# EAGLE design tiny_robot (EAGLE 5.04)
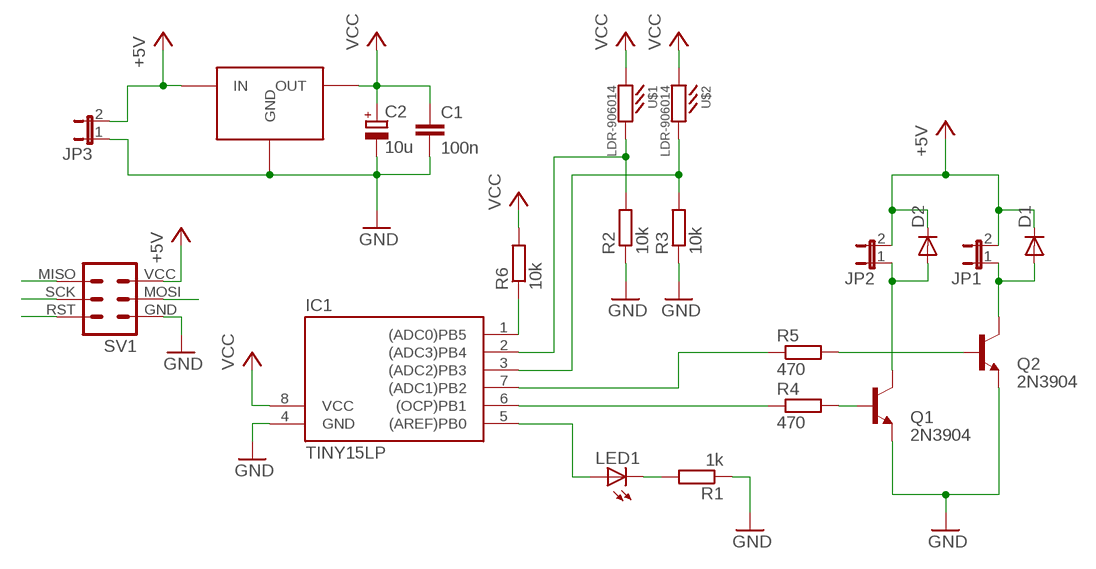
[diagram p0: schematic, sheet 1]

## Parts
C1  100n  C-EU025-025X050  [C025-025X050]
C2  10u  CPOL-EUE2,5-6E  [E2,5-6E]
D1  1N4148DO35-7  [DO35-7]
D2  1N4148DO35-7  [DO35-7]
IC1  TINY15LP  [DIL08]
JP1  JP1E  [JP1]
JP2  JP1E  [JP1]
JP3  JP1E  [JP1]
LED1  LED3MM  [LED3MM]
Q1  2N3904  [TO92]
Q2  2N3904  [TO92]
R1  1k  R-EU_0207/2V  [0207/2V]
R2  10k  R-EU_0207/2V  [0207/2V]
R3  10k  R-EU_0207/2V  [0207/2V]
R4  470  R-EU_0207/2V  [0207/2V]
R5  470  R-EU_0207/2V  [0207/2V]
R6  10k  R-EU_0207/2V  [0207/2V]
SV1  MA03-2  [MA03-2]
U$1  LDR-906014  [LDR-906014]
U$2  LDR-906014  [LDR-906014]
U$3  MCP1700  [TO92]

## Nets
+5V: D1.C D2.C JP1.2 JP2.2 JP3.2 SV1.VCC U$3.2(IN)
GND: C1.2 C2.- IC1.4(GND) JP3.1 Q1.3(E) Q2.3(E) R1.1 R2.1 R3.1 SV1.GND U$3.3(GND)
MISO: IC1.6((OCP)PB1) R4.1 SV1.MISO
MOSI: IC1.5((AREF)PB0) LED1.A SV1.MOSI
N$2: LED1.K(C) R1.2
N$3: Q1.2(B) R4.2
N$4: Q2.2(B) R5.2
N$11: D2.A JP2.1 Q1.1(C)
N$12: D1.A JP1.1 Q2.1(C)
N$13: IC1.3((ADC2)PB3) R3.2 U$2.P$2
N$15: IC1.2((ADC3)PB4) R2.2 U$1.P$2
RST: IC1.1((ADC0)PB5) R6.1 SV1.RST
SCK: IC1.7((ADC1)PB2) R5.1 SV1.SCK
VCC: C1.1 C2.+ IC1.8(VCC) R6.2 U$1.P$1 U$2.P$1 U$3.1(OUT)

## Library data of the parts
C1 = rcl:C-EU: CAPACITOR, European symbol
C2 = rcl:CPOL-EU: POLARIZED CAPACITOR, European symbol
D1 D2 = diode:1N4148: DIODE
IC1 = atmel:TINY15L: MICROCONTROLLER 2.7 V 1 Kbytes FLASH 64 bytes EEPROM 4-channel 10 bit ADC
JP1-JP3 = jumper:JP1E: JUMPER
LED1 = led:LED: LED
Q1 Q2 = transistor-npn:2N3904: NPN Transistor
R1-R6 = rcl:R-EU_: RESISTOR, European symbol
SV1 = alex:MA03-2: PIN HEADER
U$1 U$2 = alex:LDR-906014
U$3 = alex:MCP1700

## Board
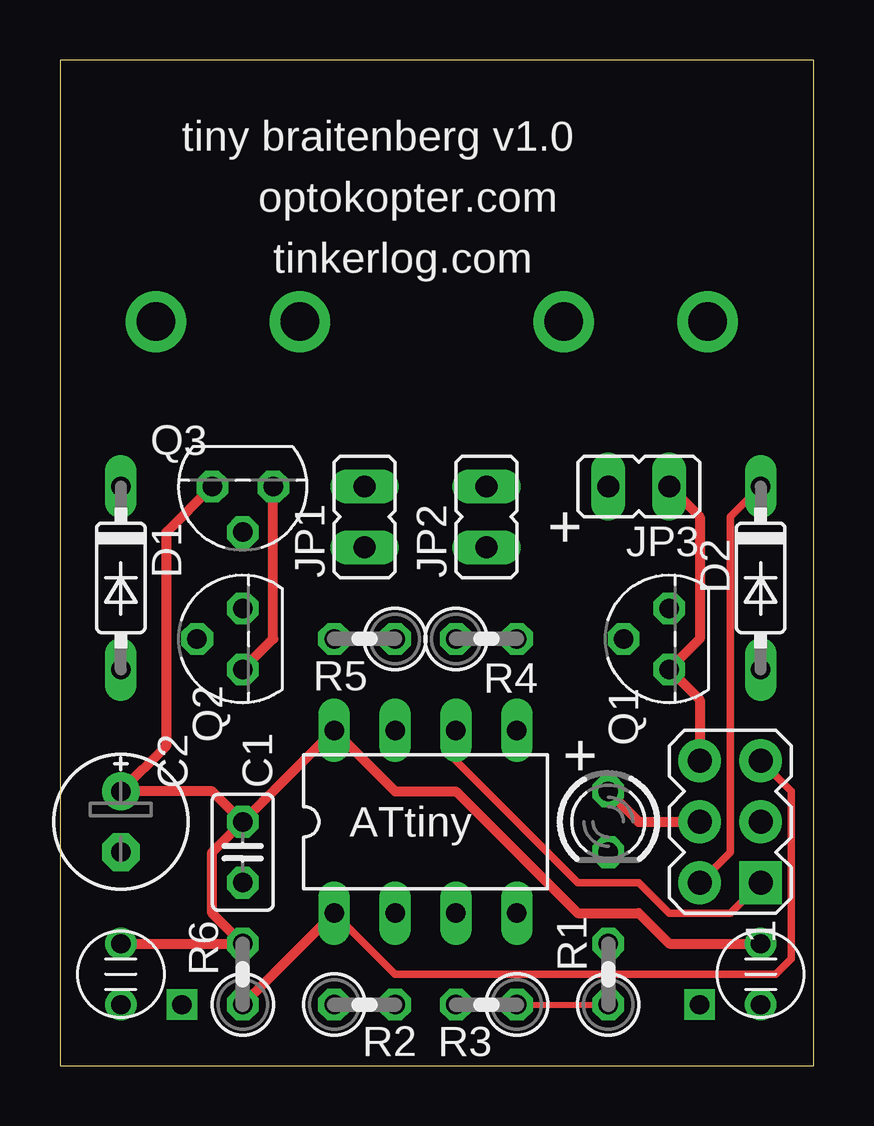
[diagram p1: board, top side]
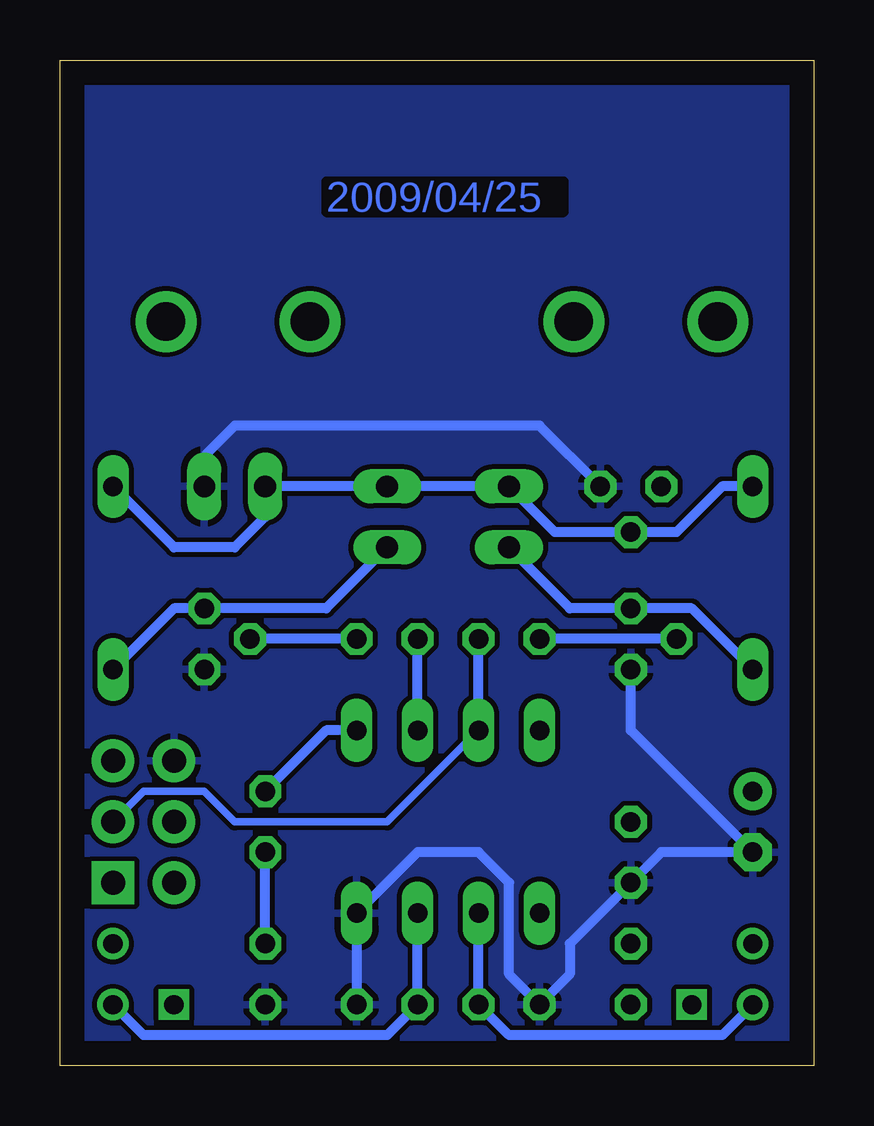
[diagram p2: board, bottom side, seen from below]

Size 31.42 x 41.9 mm. Coordinates in mm from the lower left corner, seen from the top.
Outline: 0,0 31.42,0 31.42,41.9 0,41.9 0,0
Copper layers (1*16): Top 0.035mm / dielectric 1.5mm / Bottom 0.035mm
Design rules "default": minimum track width 10mil, minimum drill 24mil, track to track 8mil, track to pad 8mil, pad to pad 8mil, via to via 8mil, smd to smd 8mil, copper to edge 40mil, drill to drill 8mil, minimum pad ring 10mil, minimum via ring 8mil, stop-mask expansion 4mil, vias tented up to drill 0mil, thermal gap 10mil

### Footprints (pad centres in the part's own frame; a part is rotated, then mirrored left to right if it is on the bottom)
C025-025X050 = drill 0.813 octagon: 1 -1.27,0; 2 1.27,0
E2,5-6E = drill 0.813 pad 1.575 round: + -1.27,0 | drill 0.813 pad 1.575 octagon: - 1.27,0
DO35-7 = drill 0.813 long: A 3.81,0; C -3.81,0
DIL08 = drill 0.813 long: 1 -3.81,-3.81; 2 -1.27,-3.81; 3 1.27,-3.81; 4 3.81,-3.81; 5 3.81,3.81; 6 1.27,3.81; 7 -1.27,3.81; 8 -3.81,3.81
JP1 = drill 0.914 long: 1 0,-1.27; 2 0,1.27
LED3MM = drill 0.813 octagon: A -1.27,0; K 1.27,0
TO92 = drill 0.813 octagon: 1 1.27,0; 2 0,1.905; 3 -1.27,0
0207/2V = drill 0.813 octagon: 1 -1.27,0; 2 1.27,0
MA03-2 = drill 1 pad 1.778 round: GND 2.54,1.27; MOSI 0,1.27; RST 2.54,-1.27; SCK 0,-1.27; VCC -2.54,1.27 | drill 1 pad 1.778 square: MISO -2.54,-1.27
LDR-906014 = drill 0.8 pad 1.27 round: P$1 0,1.27; P$2 0,-1.27

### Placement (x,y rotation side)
C1  7.62,8.89 270 top
C2  2.54,10.16 270 top
D1  2.54,20.32 270 top
D2  29.21,20.32 270 top
IC1  15.24,10.16 0 top
JP1  12.7,22.86 0 top
JP2  17.78,22.86 0 top
JP3  24.13,24.13 90 top
LED1  22.86,10.16 270 top
Q1  25.4,17.78 90 top
Q2  7.62,17.78 90 top
R1  22.86,3.81 90 top
R2  12.7,2.54 0 top
R3  17.78,2.54 180 top
R4  17.78,17.78 0 top
R5  12.7,17.78 180 top
R6  7.62,3.81 90 top
SV1  27.94,10.16 90 top
U$1  2.54,3.81 0 top
U$2  29.21,3.81 0 top
U$3  7.62,24.13 180 top

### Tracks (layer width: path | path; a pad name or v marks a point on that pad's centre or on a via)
+5V
  Top 0.305: SV1.VCC 27.94,8.89 27.94,22.86 D2.C
  Bottom 0.406: D1.C 3.81,24.13 5.71,22.23 U$3.2 10.79,22.23 JP1.2 JP2.2 JP3.2 22.86,22.86 24.13,21.59 26.67,21.59 D2.C
GND
  Top 0.254: R3.1 R1.1
  Top 0.406: U$3.3 8.89,17.78 Q2.3 | SV1.GND 26.67,15.24 Q1.3 26.67,17.78 26.67,22.86 JP3.1
  Bottom 0.406: Q2.3 7.62,13.97 C2.- 6.35,8.89 C1.2 10.16,5.08 10.16,3.81 R2.1 12.7,3.81 12.7,7.62 13.97,8.89 16.51,8.89 IC1.4 R3.1 | JP3.1 25.4,25.4 24.13,26.67 11.43,26.67 U$3.3
  pour Bottom: 0,41.91 0,0 31.75,0 31.75,41.91
MISO
  Top 0.305: SV1.MISO 27.94,6.35 25.4,6.35 24.13,7.62 21.59,7.62 16.51,12.7 16.51,13.34
  Top 0.406: IC1.6 16.51,13.34
  Bottom 0.406: IC1.6 R4.1
MOSI
  Top 0.406: SV1.MOSI 24.13,10.16 LED1.A
  Bottom 0.406: IC1.5 20.32,13.97 LED1.A
N$1  (via drill 1.6 pad 2.54)
  other vias: 4,31
N$2
  Bottom 0.406: R1.2 LED1.K
N$3
  Bottom 0.406: R4.2 Q1.2
N$4
  Bottom 0.406: Q2.2 R5.2
N$5  (via drill 1.6 pad 2.54)
  other vias: 10,31
N$6  (via drill 1.6 pad 2.54)
  other vias: 27,31
N$7  (via drill 1.6 pad 2.54)
  other vias: 21,31
N$8  (via drill 0.8 pad 1.27)
  other vias: 5.08,2.54
N$9  (via drill 0.8 pad 1.27)
  other vias: 26.67,2.54
N$11
  Bottom 0.406: JP2.1 20.32,19.05 Q1.1 26.67,19.05 D2.A
N$12
  Bottom 0.406: JP1.1 10.16,19.05 Q2.1 5.08,19.05 D1.A
N$13
  Bottom 0.406: IC1.3 R3.2 17.78,1.27 27.94,1.27 U$2.P$2
N$15
  Bottom 0.406: IC1.2 R2.2 12.7,1.27 3.81,1.27 U$1.P$2
RST
  Top 0.305: SV1.RST 30.48,11.43 30.48,4.45 29.84,3.81 13.97,3.81 IC1.1
  Top 0.406: R6.1 IC1.1
SCK
  Bottom 0.305: SV1.SCK 27.94,11.43 25.4,11.43 24.13,10.16 17.78,10.16 IC1.7
  Bottom 0.406: IC1.7 R5.1
VCC
  Top 0.406: C1.1 6.35,11.43 C2.+ 4.45,13.34 4.45,22.23 U$3.1 | C1.1 IC1.8 13.97,11.43 16.51,11.43 21.59,6.35 24.13,6.35 25.4,5.08 U$2.P$1 | C1.1 6.35,8.89 6.35,6.35 R6.2 U$1.P$1

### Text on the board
Bottom: 2009/04/25
tPlace: tiny braitenberg v1.0 | optokopter.com | tinkerlog.com | + | + | ATtiny
tNames: Q3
